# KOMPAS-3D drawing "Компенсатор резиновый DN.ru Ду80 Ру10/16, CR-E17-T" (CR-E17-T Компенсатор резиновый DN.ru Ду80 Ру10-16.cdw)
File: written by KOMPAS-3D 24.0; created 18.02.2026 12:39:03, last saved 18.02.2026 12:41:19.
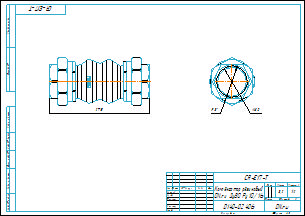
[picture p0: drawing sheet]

Document properties: Типовые: Типовые; Автор: DN.RU; Форматы листов документа: A3; Полное имя файла: CR-E17-T Компенсатор резиновый DN.ru Ду80 Ру10-16.m3d; Масса: 3.2; Наименование: Компенсатор резиновый DN.ru Ду80 Ру10/16; Количество листов документа: 1; Комментарий: D140-02406; Примечание: D140-02406

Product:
- Body: Твердое тело1  | qty 1
    Масса: 9.100291
- Part/product: Компенсатор резиновый DN.ru Ду80 Ру10/16  | designation CR-E17-T
    Масса: 3.2
    Раздел спецификации: Прочие изделия
    Форматы листов документа: A3
    Комментарий: D140-02406
    Примечание: D140-02406
    additional columns: Типовые

Views: Вид 1, Справа, Проекционный вид 2
Referenced files in D:\Работа\Компенсаторы\CR-Е17-T Компенсатор резиновый DN.ru Ду15-80\DN80\: CR-E17-T Компенсатор резиновый DN.ru Ду80 Ру10-16.m3d, CR-E17-T Компенсатор резиновый DN.ru Ду80 Ру10-16.cdw
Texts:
  Линейный размер
  CR-E17-T
  Диаметральный размер
  Компенсатор резиновый
  DN.ru Ду80 Ру10/16
  Твердое тело1
  Компенсатор резиновый DN.ru Ду80 Ру10/16
  CR-E17-T Компенсатор резиновый DN.ru Ду80 Ру10/16
Dimensions and other numbers on the sheet: 0; 3; 2; 4; 275; 80; 1:2; 1; 3,2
